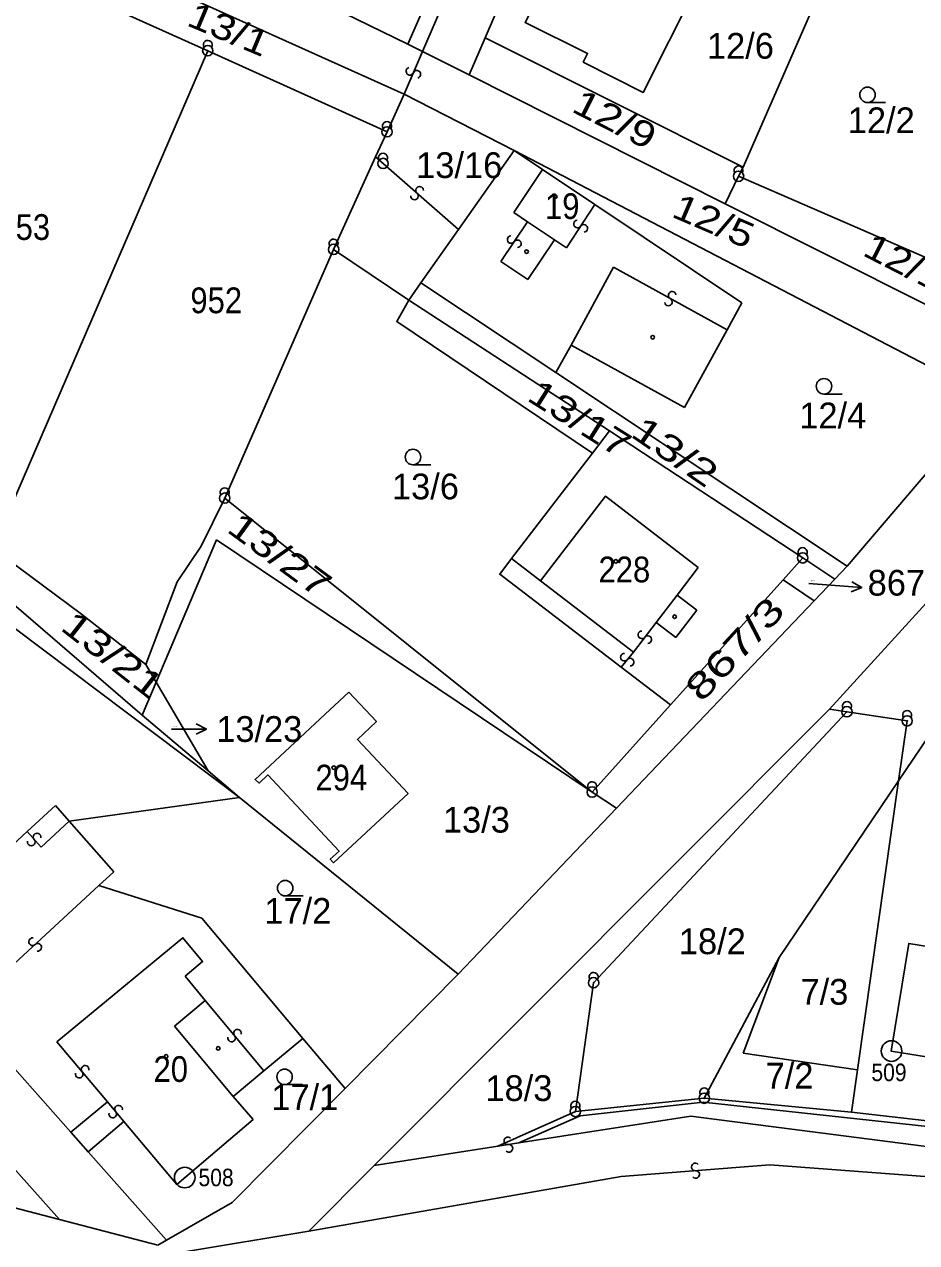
# Model space of a CAD drawing. Extents: x -680102 to -677253, y -1007548 to -1006096.
# Drawn here: x -679757 to -679670.3, y -1007081.9 to -1006963.5 of the extents above; entities that cross this region are included whole.
import ezdxf
from ezdxf.enums import TextEntityAlignment as Align

# ---------------------------------------------------------------- set-up
doc = ezdxf.new("R2010")
doc.units = 0
for name, color, linetype, lineweight in [('1', 7, 'Continuous', 25), ('16', 7, 'Continuous', 25), ('24', 7, 'Continuous', 25), ('25', 7, 'Continuous', 25), ('4', 7, 'Continuous', 25)]:
    doc.layers.add(name, color=color, linetype=linetype, lineweight=lineweight)
for name, color, linetype in [('17', 7, 'Continuous'), ('18', 7, 'Continuous'), ('19', 7, 'Continuous')]:
    doc.layers.add(name, color=color, linetype=linetype)

msp = doc.modelspace()

# ---------------------------------------------------------------- linework, layer by layer
at = {"layer": '1'}
for p, q in [((-679704.22, -1006946.09), (-679712.27, -1006964.85)), ((-679712.27, -1006964.85), (-679713.82, -1006968.45)), ((-679719.76, -1006965.46), (-679718.34, -1006966.18)), ((-679739.2, -1006966.09), (-679760.08, -1007014.44)), ((-679720.12, -1006970.3), (-679709.44, -1006975.78)), ((-679722.9, -1006976.41), (-679726.98, -1006985.39)), ((-679709.44, -1006975.78), (-679714.84, -1006983.45)), ((-679709.44, -1006975.78), (-679663.2, -1006999.87)), ((-679687.64, -1006978.29), (-679688.93, -1006980.96)), ((-679726.98, -1006985.39), (-679719.66, -1006990.31)), ((-679705.38, -1006997.36), (-679718.49, -1006988.65)), ((-679719.66, -1006990.31), (-679700.18, -1007003.02)), ((-679687.33, -1006990.58), (-679688.76, -1006993.2)), ((-679688.76, -1006993.2), (-679692.88, -1007000.74)), ((-679745.57, -1007030.62), (-679787.16, -1006994.88)), ((-679692.88, -1007000.74), (-679703.91, -1006994.68)), ((-679663.2, -1006999.87), (-679677.08, -1007016.16)), ((-679744.22, -1007027.43), (-679738.37, -1007013.6)), ((-679738.37, -1007013.6), (-679701.86, -1007038.1)), ((-679677.08, -1007016.16), (-679678.28, -1007017.42)), ((-679683.31, -1007017.48), (-679680.29, -1007019.53)), ((-679739.15, -1007036.05), (-679744.22, -1007027.43)), ((-679694.25, -1007029.64), (-679701.86, -1007038.1)), ((-679701.72, -1007056.62), (-679677.11, -1007030.3)), ((-679672.09, -1007037.02), (-679683.68, -1007054.16)), ((-679676.09, -1007065.08), (-679672.09, -1007037.02)), ((-679701.86, -1007038.1), (-679699.51, -1007039.68)), ((-679752.66, -1007040.94), (-679736.11, -1007038.63)), ((-679714.88, -1007055.79), (-679736.11, -1007038.63)), ((-679756.75, -1007041.95), (-679754.01, -1007039.42)), ((-679699.51, -1007039.68), (-679714.88, -1007055.79)), ((-679749.79, -1007047.19), (-679748.32, -1007045.84)), ((-679739.77, -1007050.36), (-679749.79, -1007047.19)), ((-679683.68, -1007054.16), (-679690.97, -1007067.84)), ((-679687.18, -1007063.47), (-679683.68, -1007054.16)), ((-679701.72, -1007056.62), (-679703.49, -1007069.14)), ((-679676.09, -1007065.08), (-679687.18, -1007063.47)), ((-679676.67, -1007069.21), (-679676.09, -1007065.08)), ((-679736.74, -1007067.68), (-679734.79, -1007069.9)), ((-679742.2, -1007076.21), (-679747.35, -1007070.09)), ((-679734.79, -1007069.9), (-679742.2, -1007076.21)), ((-679703.49, -1007069.14), (-679711.02, -1007072.51)), ((-679676.67, -1007069.21), (-679658.21, -1007071.31)), ((-679711.02, -1007072.51), (-679723.03, -1007074.38)), ((-679743.22, -1007081.64), (-679750.83, -1007073.05)), ((-679741.46, -1007082.75), (-679729.37, -1007080.74))]:
    msp.add_line(p, q, dxfattribs=at)
for points in [[(-679707.75, -1006937.97), (-679711.98, -1006947.65), (-679719.76, -1006965.46)], [(-679675.31, -1006950.19), (-679677.98, -1006956.3), (-679678.38, -1006957.22), (-679687.2, -1006977.42)], [(-679719.76, -1006965.46), (-679735.92, -1006957.56), (-679746.84, -1006952.73)], [(-679720.12, -1006970.3), (-679751.82, -1006956.03), (-679752.24, -1006955.84)], [(-679721.79, -1006973.97), (-679739.2, -1006966.09), (-679756.81, -1006958.18)], [(-679712.27, -1006964.85), (-679687.2, -1006977.42), (-679687.64, -1006978.29), (-679659.02, -1006990.71)], [(-679718.34, -1006966.18), (-679713.82, -1006968.45), (-679688.93, -1006980.96), (-679659.65, -1006995.68)], [(-679720.12, -1006970.3), (-679721.79, -1006973.97), (-679722.9, -1006976.41)], [(-679709.44, -1006975.78), (-679706.7, -1006977.62), (-679701.59, -1006981.04), (-679687.33, -1006990.58)], [(-679714.84, -1006983.45), (-679718.49, -1006988.65), (-679719.66, -1006990.31)], [(-679701.86, -1007038.1), (-679737.56, -1007009.55), (-679726.98, -1006985.39)], [(-679719.66, -1006990.31), (-679720.84, -1006992.4), (-679701.84, -1007005.19)], [(-679677.08, -1007016.16), (-679705.38, -1006997.36), (-679703.91, -1006994.68)], [(-679678.79, -1007030.04), (-679652.35, -1007001.03), (-679646.69, -1006994.81)], [(-679736.11, -1007038.63), (-679787.94, -1006999.66), (-679789.24, -1007008.41)], [(-679700.18, -1007003.02), (-679701.84, -1007005.19), (-679709.69, -1007015.43)], [(-679700.18, -1007003.02), (-679681.41, -1007015.36), (-679678.28, -1007017.42)], [(-679751.46, -1007020.82), (-679760.08, -1007014.44), (-679767, -1007009.31)], [(-679745.22, -1007025.72), (-679742.19, -1007017.67), (-679739.84, -1007014.22), (-679737.56, -1007009.55)], [(-679709.69, -1007015.43), (-679710.84, -1007016.94), (-679699.06, -1007025.97), (-679694.25, -1007029.64)], [(-679694.25, -1007029.64), (-679683.31, -1007017.48), (-679681.41, -1007015.36)], [(-679678.28, -1007017.42), (-679680.29, -1007019.53), (-679699.51, -1007039.68)], [(-679744.22, -1007027.43), (-679745.22, -1007025.72), (-679751.46, -1007020.82)], [(-679662.59, -1007022.98), (-679668.44, -1007031.62), (-679672.09, -1007037.02), (-679671.26, -1007031.19)], [(-679736.11, -1007038.63), (-679739.15, -1007036.05), (-679745.57, -1007030.62), (-679744.22, -1007027.43)], [(-679729.37, -1007080.74), (-679723.03, -1007074.38), (-679678.79, -1007030.04)], [(-679671.26, -1007031.19), (-679677.11, -1007030.3), (-679678.79, -1007030.04)], [(-679790.99, -1007039.99), (-679774.85, -1007055.84), (-679753.61, -1007079.63)], [(-679748.32, -1007045.84), (-679752.66, -1007040.94), (-679754.01, -1007039.42)], [(-679767.86, -1007052.2), (-679758.16, -1007043.25), (-679756.75, -1007041.95)], [(-679725.86, -1007066.9), (-679729.96, -1007062.03), (-679739.77, -1007050.36)], [(-679714.88, -1007055.79), (-679725.86, -1007066.9), (-679736.82, -1007077.98)], [(-679747.35, -1007070.09), (-679750.83, -1007073.05), (-679752.52, -1007071.14), (-679762.97, -1007059.37)], [(-679729.96, -1007062.03), (-679733.75, -1007065.18), (-679736.74, -1007067.68)], [(-679703.49, -1007069.14), (-679690.97, -1007067.84), (-679676.67, -1007069.21)], [(-679762.72, -1007077.25), (-679753.61, -1007079.63), (-679744.06, -1007082.12)], [(-679736.82, -1007077.98), (-679743.22, -1007081.64), (-679744.06, -1007082.12)]]:
    msp.add_lwpolyline(points, dxfattribs=at)
for points in [[(-679703.75, -1006954.19), (-679691.88, -1006960.13), (-679696.9, -1006970.14), (-679702.73, -1006967.2), (-679702.3, -1006966.35), (-679708.37, -1006963.36)], [(-679725.5, -1007028.39), (-679722.82, -1007031.26), (-679724.67, -1007032.99), (-679719.74, -1007038.24), (-679726.98, -1007044.97), (-679727.3, -1007044.63), (-679726.44, -1007043.84), (-679733.36, -1007036.43), (-679734.22, -1007037.23), (-679734.6, -1007036.88), (-679727.36, -1007030.12)]]:
    msp.add_lwpolyline(points, close=True, dxfattribs=at)
at = {"layer": '16'}
for p, q in [((-679680.82, -1007017.84), (-679678.67, -1007018.01)), ((-679678.67, -1007018.01), (-679675.68, -1007018.245)), ((-679742.72, -1007031.98), (-679742.33, -1007031.98)), ((-679742.33, -1007031.98), (-679739.33, -1007031.98))]:
    msp.add_line(p, q, dxfattribs=at)
for points in [[(-679676.637, -1007017.669), (-679675.68, -1007018.245), (-679676.716, -1007018.665)], [(-679740.33, -1007031.481), (-679739.33, -1007031.98), (-679740.33, -1007032.48)]]:
    msp.add_lwpolyline(points, dxfattribs=at)
at = {"layer": '24'}
for centre, radius in [((-679739.2, -1006966.09), 0.5), ((-679739.2, -1006966.09), 0.022), ((-679721.79, -1006973.97), 0.5), ((-679721.79, -1006973.97), 0.022), ((-679722.18, -1006977.04), 0.5), ((-679722.18, -1006977.04), 0.022), ((-679687.64, -1006978.29), 0.5), ((-679687.64, -1006978.29), 0.022), ((-679726.98, -1006985.39), 0.5), ((-679726.98, -1006985.39), 0.022), ((-679737.56, -1007009.55), 0.5), ((-679737.56, -1007009.55), 0.022), ((-679681.41, -1007015.36), 0.5), ((-679681.41, -1007015.36), 0.022), ((-679677.11, -1007030.3), 0.5), ((-679677.11, -1007030.3), 0.022), ((-679671.26, -1007031.19), 0.5), ((-679671.26, -1007031.19), 0.022), ((-679701.86, -1007038.1), 0.5), ((-679701.86, -1007038.1), 0.022), ((-679701.72, -1007056.62), 0.5), ((-679701.72, -1007056.62), 0.022), ((-679672.78, -1007063.26), 1), ((-679672.78, -1007063.26), 0.032), ((-679690.97, -1007067.84), 0.5), ((-679703.49, -1007069.14), 0.5), ((-679690.97, -1007067.84), 0.022), ((-679703.49, -1007069.14), 0.022), ((-679741.44, -1007075.55), 1), ((-679741.44, -1007075.55), 0.032)]:
    msp.add_circle(centre, radius, dxfattribs=at)
for centre in [(-679739.201, -1006965.527), (-679721.791, -1006973.407), (-679722.181, -1006976.477), (-679687.641, -1006977.727), (-679726.981, -1006984.827), (-679737.561, -1007008.987), (-679681.411, -1007014.797), (-679677.111, -1007029.737), (-679671.261, -1007030.627), (-679701.861, -1007037.537), (-679701.721, -1007056.057), (-679690.971, -1007067.277), (-679703.491, -1007068.577)]:
    msp.add_arc(centre, 0.437, 328.35109, 209.97456, dxfattribs=at)
at = {"layer": '25'}
for p, q in [((-679675.11, -1006971.13), (-679673.36, -1006971.13)), ((-679679.34, -1006999.44), (-679677.59, -1006999.44)), ((-679719.27, -1007006.31), (-679717.52, -1007006.31)), ((-679731.68, -1007048.19), (-679729.93, -1007048.19)), ((-679731.74, -1007066.52), (-679729.99, -1007066.52))]:
    msp.add_line(p, q, dxfattribs=at)
for centre, radius in [((-679675.11, -1006970.38), 0.75), ((-679705.44, -1006980.27), 0.175), ((-679708.23, -1006985.61), 0.175), ((-679695.98, -1006993.92), 0.175), ((-679679.34, -1006998.69), 0.75), ((-679719.27, -1007005.56), 0.75), ((-679699.56, -1007015.69), 0.175), ((-679693.85, -1007021.07), 0.175), ((-679726.96, -1007035.73), 0.175), ((-679731.68, -1007047.44), 0.75), ((-679738.19, -1007063), 0.175), ((-679743.25, -1007063.78), 0.175), ((-679731.74, -1007065.77), 0.75)]:
    msp.add_circle(centre, radius, dxfattribs=at)
for centre, radius, start, end in [((-679719.567, -1006968.09), 0.369, 103.96173, 335.61471), ((-679718.894, -1006968.388), 0.368, 283.91442, 156.22889), ((-679719.116, -1006980.205), 0.369, 175.96004, 47.93047), ((-679718.626, -1006979.655), 0.368, 356.02765, 228.42005), ((-679703.285, -1006982.935), 0.368, 93.91558, 326.09632), ((-679702.675, -1006983.347), 0.369, 273.73357, 146.2202), ((-679709.735, -1006984.434), 0.368, 93.70923, 325.96711), ((-679709.125, -1006984.848), 0.369, 273.57851, 145.84941), ((-679694.09, -1006989.849), 0.367, 8.37465, 240.72049), ((-679694.451, -1006990.491), 0.369, 188.41709, 60.3562), ((-679697.039, -1007022.833), 0.367, 89.62432, 321.85409), ((-679696.461, -1007023.288), 0.369, 269.6916, 141.98458), ((-679698.732, -1007025.002), 0.369, 87.82202, 319.5833), ((-679698.168, -1007025.476), 0.368, 267.58241, 140.07584), ((-679756.347, -1007042.952), 0.368, 168.8999, 41.14229), ((-679755.791, -1007042.469), 0.368, 348.87609, 221.09516), ((-679756.217, -1007052.638), 0.368, 80.29047, 312.2447), ((-679755.723, -1007053.184), 0.369, 259.85008, 132.0373), ((-679736.886, -1007061.992), 0.368, 167.13499, 39.11542), ((-679736.315, -1007061.527), 0.368, 346.74018, 219.26925), ((-679751.694, -1007065.504), 0.368, 167.18145, 39.48691), ((-679751.125, -1007065.037), 0.369, 347.32238, 219.47998), ((-679747.866, -1007068.905), 0.369, 347.32238, 219.54645), ((-679748.433, -1007069.375), 0.368, 167.67301, 39.70617), ((-679710.052, -1007071.985), 0.368, 46.32234, 278.11034), ((-679709.946, -1007072.714), 0.368, 226.29739, 98.43916), ((-679691.845, -1007074.514), 0.367, 41.83236, 273.90976), ((-679691.796, -1007075.248), 0.369, 221.6999, 93.88796)]:
    msp.add_arc(centre, radius, start, end, dxfattribs=at)
at = {"layer": '4'}
for p, q in [((-679722.9, -1006976.41), (-679714.84, -1006983.45)), ((-679709.48, -1006981.8), (-679706.7, -1006977.62)), ((-679704.37, -1006985.23), (-679701.59, -1006981.04)), ((-679709.48, -1006981.8), (-679708.14, -1006982.7)), ((-679710.72, -1006986.57), (-679708.14, -1006982.7)), ((-679708.14, -1006982.7), (-679705.53, -1006984.45)), ((-679708.1, -1006988.32), (-679705.53, -1006984.45)), ((-679705.53, -1006984.45), (-679704.37, -1006985.23)), ((-679710.72, -1006986.57), (-679708.1, -1006988.32)), ((-679703.91, -1006994.68), (-679699.78, -1006987.13)), ((-679699.78, -1006987.13), (-679688.76, -1006993.2)), ((-679709.69, -1007015.43), (-679706.87, -1007017.59)), ((-679706.87, -1007017.59), (-679697.85, -1007024.5)), ((-679691.7, -1007020.45), (-679693.62, -1007018.98)), ((-679693.72, -1007023.09), (-679691.7, -1007020.45)), ((-679697.85, -1007024.5), (-679695.64, -1007021.62)), ((-679695.64, -1007021.62), (-679693.72, -1007023.09)), ((-679697.85, -1007024.5), (-679699.06, -1007025.97)), ((-679755.4, -1007043.47), (-679752.66, -1007040.94)), ((-679755.4, -1007043.47), (-679756.75, -1007041.95)), ((-679762.16, -1007058.62), (-679749.79, -1007047.19)), ((-679741.41, -1007055.98), (-679739.45, -1007058.34)), ((-679742.44, -1007060.84), (-679739.45, -1007058.34)), ((-679739.45, -1007058.34), (-679733.75, -1007065.18)), ((-679736.74, -1007067.68), (-679742.44, -1007060.84)), ((-679748.95, -1007068.19), (-679753.86, -1007062.35)), ((-679752.52, -1007071.14), (-679748.95, -1007068.19)), ((-679747.35, -1007070.09), (-679748.95, -1007068.19)), ((-679703.02, -1007069.54), (-679708.98, -1007072.19)), ((-679692.29, -1007069.6), (-679638.92, -1007076.45)), ((-679699.05, -1007075.43), (-679684.6, -1007074.32)), ((-679729.37, -1007080.74), (-679699.05, -1007075.43))]:
    msp.add_line(p, q, dxfattribs=at)
for points in [[(-679710.59, -1006948.27), (-679718.34, -1006966.18), (-679720.12, -1006970.3)], [(-679691.57, -1007016.3), (-679700.56, -1007009.35), (-679706.87, -1007017.59)], [(-679695.64, -1007021.62), (-679693.62, -1007018.98), (-679691.57, -1007016.3)], [(-679753.86, -1007062.35), (-679741.62, -1007052.26), (-679739.71, -1007054.57), (-679741.41, -1007055.98)], [(-679655.63, -1007055.32), (-679671.11, -1007052.8), (-679672.81, -1007063.27), (-679657.32, -1007065.78)], [(-679703.02, -1007069.54), (-679691.07, -1007068.22), (-679658.25, -1007071.8)], [(-679692.29, -1007069.6), (-679708.98, -1007072.19), (-679711.02, -1007072.51)], [(-679684.6, -1007074.32), (-679645.4, -1007077.27), (-679613.29, -1007081.02)]]:
    msp.add_lwpolyline(points, dxfattribs=at)

# ---------------------------------------------------------------- texts
at = {"layer": '16'}
for s, p in [('867/4', (-679675.1, -1007019.02)), ('13/23', (-679738.38, -1007033.23))]:
    msp.add_text(s, height=2.5, dxfattribs=at).set_placement(p)
at = {"layer": '17', "width": 0.9}
for s, p in [('509', (-679671.32, -1007066.18)), ('508', (-679736.69, -1007076.39))]:
    msp.add_text(s, height=1.7, dxfattribs=at).set_placement(p, align=Align.RIGHT)
at = {"layer": '18'}
for s, rotation, width, p in [('13/1', 337.203, 1.25, (-679737.63, -1006965.162)), ('12/9', 333.003, 1.3, (-679700.225, -1006973.865)), ('12/10', 333.003, 1.25, (-679671.064, -1006988.285)), ('13/27', 323.803, 1.35, (-679732.93, -1007016.077)), ('13/21', 321.903, 1.35, (-679749.193, -1007025.754))]:
    msp.add_text(s, height=2.5, rotation=rotation, dxfattribs=dict(at, width=width)).set_placement(p, align=Align.CENTER)
for s, height, p in [('12/6', 2.5, (-679690.71, -1006966.87)), ('12/2', 2.5, (-679677.03, -1006974.1)), ('13/16', 2.5, (-679718.96, -1006978.46)), ('12/4', 2.5, (-679681.74, -1007002.77)), ('13/6', 2.5, (-679721.31, -1007009.67)), ('867/4', 0.1, (-679680.62, -1007017.64)), ('13/23', 0.1, (-679742.52, -1007031.78)), ('13/3', 2.5, (-679716.36, -1007042.04)), ('17/2', 2.5, (-679733.71, -1007050.9)), ('18/2', 2.5, (-679693.44, -1007053.85)), ('7/3', 2.5, (-679681.62, -1007058.76)), ('7/2', 2.5, (-679685.01, -1007066.9)), ('17/1', 2.5, (-679733.03, -1007068.99)), ('18/3', 2.5, (-679712.23, -1007068.11))]:
    msp.add_text(s, height=height, dxfattribs=at).set_placement(p)
for s, rotation, width, p in [('12/5', 336.803, 1.25, (-679694.278, -1006982.175)), ('13/17', 327.803, 1.3, (-679708.325, -1006999.988)), ('13/2', 325.503, 1.4, (-679698.262, -1007003.489)), ('867/3', 47.1, 1.45, (-679691.23, -1007029.488))]:
    msp.add_text(s, height=2.5, rotation=rotation, dxfattribs=dict(at, width=width)).set_placement(p)
at = {"layer": '18', "width": 0.9}
for s, p in [('953', (-679757.03, -1006984.47)), ('952', (-679738.38, -1006991.59))]:
    msp.add_text(s, height=2.5, dxfattribs=at).set_placement(p, align=Align.CENTER)
at = {"layer": '19', "width": 0.9}
for s, p in [('19', (-679706.44, -1006982.44)), ('228', (-679701.24, -1007017.73)), ('294', (-679728.74, -1007037.95)), ('20', (-679744.47, -1007066.26))]:
    msp.add_text(s, height=2.5, dxfattribs=at).set_placement(p)

doc.saveas('drawing.dxf')
